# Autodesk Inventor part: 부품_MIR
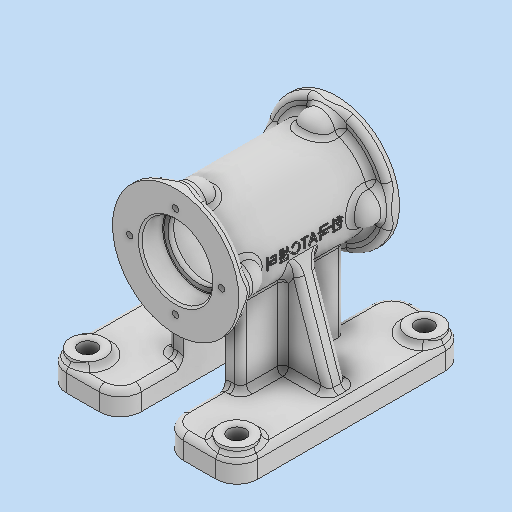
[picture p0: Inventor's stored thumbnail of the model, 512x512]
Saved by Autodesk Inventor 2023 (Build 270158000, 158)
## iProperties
Created: 2026-06
Part Number: 부품_MIR
Material: 일반
Document SubType Name: Modeling
Designer: home
Density: 1 g/cm^3
Appearance: 기본값
Author: home
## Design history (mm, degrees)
derived "부품.ipt"
  sketch "스케치1"
    geometry: L1 (-50, 60)-(50, 60) reference; L2 (50, 60)-(50, -60) reference; L3 (50, -60)-(-50, -60) reference; L4 (-50, -60)-(-50, 60) reference; L5 (-50, 60)-(50, -60) reference; L6 (50, 60)-(-50, -60) reference; 1 further point
  sketch "스케치2"
    geometry: L1 (11, 60)-(11, -60) reference; L2 (-11, 60)-(-11, -60) reference; L3 (50, 60)-(50, -60) reference; L4 (-50, -60)-(-50, 60) reference; L5 (-50, 60)-(50, 60) reference; L6 (11, 60)-(-11, 60) reference; L7 (50, -60)-(-50, -60) reference; L8 (11, -60)-(-11, -60) reference; 1 further point
  sketch "스케치7"
    geometry: C1 r 33 at (0, 70) reference; 1 further point
  sketch "스케치8"
    geometry: L1 (-37, -37)-(-103, -37) reference; L2 (-37, 37)-(-103, 37) reference; L3 (-70, -37)-(-70, 37) reference; L4 (-95, -37)-(-95, 37) reference; L5 (-95, -37)-(-70, -37) reference; L6 (-70, 37)-(-70, -37) reference; L7 (-70, 37)-(-95, 37) reference; L8 (-70, -37)-(-70, 37) reference; L9 (-103, 42)-(-37, 42) reference; 1 further point
  sketch "스케치11"
    geometry: L1 (-103, 42)-(-37, 42) reference; L2 (-88.5, 42)-(-88.5, 30) reference; L3 (-88.5, 30)-(-86, 30) reference; L4 (-86, 30)-(-86, 27) reference; L5 (-86, 27)-(-90, 27) reference; L6 (-90, 27)-(-90, 0) reference; L7 (-95, -37)-(-95, 37) reference; L8 (-95, 0)-(-37, 0) reference; L9 (-70, 42)-(-70, -47.015) reference; L10 (-88.5, 42)-(-70, 42) reference; L11 (-37, 37)-(-103, 37) reference; L12 (-70, 42)-(-70, 0) reference; L13 (-70, 0)-(-90, 0) reference; 1 further point
  sketch "스케치13"
    geometry: L1 (-11, 27)-(-19, 27) reference; L2 (-19, 27)-(-19, -27) reference; L3 (-19, -27)-(-11, -27) reference; L4 (-11, -27)-(-11, 27) reference; L5 (-11, 49)-(-11, -49) reference; 2 further points
  sketch "스케치14"
    geometry: L1 (-24.587, 65.475)-(-43, 12) reference; L2 (-19, 12)-(-19, 53.752) reference; L3 (-19, 12)-(-19, 53.752) reference; L4 (-19, 12)-(-43, 12) reference; L5 (-50, 12)-(-50, 0) reference; A1 r 25 centre (0, 70) between (-19, 53.752) and (-19, 53.752) reference; A2 r 25 centre (0, 70) between (-24.587, 65.475) and (-19, 53.752) reference; 2 further points
  sketch "스케치15"
    geometry: L1 (39, -49)-(-39, -49) reference; L2 (-39, -49)-(-39, 49) reference; L3 (-39, 49)-(39, 49) reference; L4 (39, 49)-(39, -49) reference; L5 (39, -49)-(-39, 49) reference; L6 (-39, -49)-(39, 49) reference; C1 r 9 at (39, 49) reference; C2 r 9 at (-39, 49) reference; C3 r 9 at (39, -49) reference; C4 r 9 at (-39, -49) reference; C5 r 4.5 at (39, 49) reference; C6 r 4.5 at (-39, 49) reference; C7 r 4.5 at (-39, -49) reference; C8 r 4.5 at (39, -49) reference; 1 further point
  sketch "스케치16"
    geometry: C1 r 33 at (0, 0) reference; A1 r 24 centre (0, 0) between (24, 0) and (0, -24) reference; 3 further points
  sketch "스케치17"
    geometry: L1 (-92.379, 42)-(-95.621, 42) reference; L2 (-94, 42)-(-94, 29) reference; L3 (-94, 37)-(-94, 19.967) reference; C1 r 8 at (-94, 32) reference; 1 further point
  sketch "스케치18"
    geometry: C1 r 18.5 at (0, 0) reference; C2 r 18.5 at (0, 0) reference; 1 further point
  sketch "스케치22"
    geometry: C1 r 16 at (0, -24) reference; C2 r 20 at (0, -24) reference; 1 further point
  sketch "스케치23"
    geometry: L1 (0, -49)-(0, 49) reference; 3 further points
  node "작업 평면1"
  node "작업 평면2"
feature "솔리드1::부품.ipt" dims "d0" = 10
tag "피쳐 태그1"
node "솔리드1"
